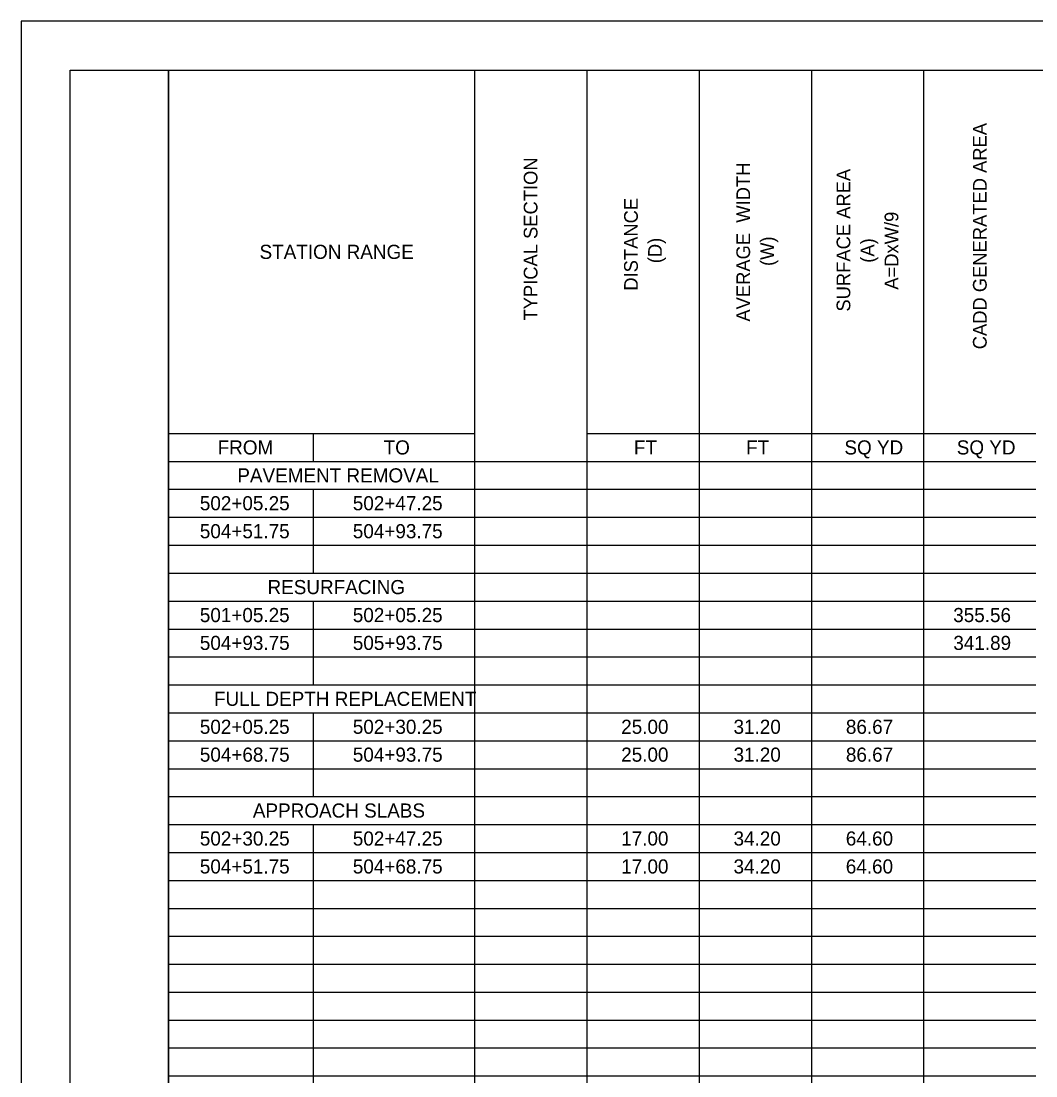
# Model space of a CAD drawing. Extents: x 0 to 34, y 0 to 22.
# Drawn here: x 0 to 10.32, y 11.28 to 22 of the extents above; entities that cross this region are included whole.
import ezdxf

# ---------------------------------------------------------------- set-up
doc = ezdxf.new("R2010")
doc.units = 0
for name, color, linetype in [('SH_Border', 7, 'Continuous'), ('SH_Cut_Line', 7, 'Continuous'), ('SH_Text', 7, 'Continuous')]:
    doc.layers.add(name, color=color, linetype=linetype)

msp = doc.modelspace()

# ---------------------------------------------------------------- linework, layer by layer
at = {"layer": 'SH_Border'}
for points in [[(0.5, 21.5), (1.5, 21.5), (1.5, 0.5), (0.5, 0.5)], [(1.5, 21.5), (33.5, 21.5), (33.5, 0.5), (1.5, 0.5)]]:
    msp.add_lwpolyline(points, close=True, dxfattribs=at)
at = {"layer": 'SH_Cut_Line'}
msp.add_lwpolyline([(0, 0), (34, 0), (34, 22), (0, 22)], close=True, dxfattribs=at)
at = {"layer": 'SH_Text'}
for p, q in [((1.5, 21.5), (2.969, 21.5)), ((1.5, 21.5), (1.5, 21.216)), ((2.969, 21.5), (4.609, 21.5)), ((4.609, 21.5), (8.033, 21.5)), ((4.609, 21.5), (4.609, 21.216)), ((5.75, 21.5), (5.75, 21.216)), ((6.892, 21.5), (6.892, 21.216)), ((8.033, 21.5), (10.315, 21.5)), ((8.033, 21.5), (8.033, 21.216)), ((9.174, 21.5), (9.174, 21.216)), ((1.5, 21.216), (1.5, 20.932)), ((4.609, 21.216), (4.609, 20.932)), ((5.75, 21.216), (5.75, 20.932)), ((6.892, 21.216), (6.892, 20.932)), ((8.033, 21.216), (8.033, 20.932)), ((9.174, 21.216), (9.174, 20.932)), ((1.5, 20.932), (1.5, 20.649)), ((4.609, 20.932), (4.609, 20.649)), ((5.75, 20.932), (5.75, 20.649)), ((6.892, 20.932), (6.892, 20.649)), ((8.033, 20.932), (8.033, 20.649)), ((9.174, 20.932), (9.174, 20.649)), ((1.5, 20.649), (1.5, 20.081)), ((4.609, 20.649), (4.609, 20.081)), ((5.75, 20.649), (5.75, 20.081)), ((6.892, 20.649), (6.892, 20.081)), ((8.033, 20.649), (8.033, 20.081)), ((9.174, 20.649), (9.174, 20.081)), ((1.5, 20.081), (1.5, 19.797)), ((4.609, 20.081), (4.609, 19.797)), ((5.75, 20.081), (5.75, 19.797)), ((6.892, 20.081), (6.892, 19.797)), ((8.033, 20.081), (8.033, 19.797)), ((9.174, 20.081), (9.174, 19.797)), ((1.5, 19.797), (1.5, 19.514)), ((4.609, 19.797), (4.609, 19.514)), ((5.75, 19.797), (5.75, 19.514)), ((6.892, 19.797), (6.892, 19.514)), ((8.033, 19.797), (8.033, 19.514)), ((9.174, 19.797), (9.174, 19.514)), ((1.5, 19.514), (1.5, 19.23)), ((4.609, 19.514), (4.609, 19.23)), ((5.75, 19.514), (5.75, 19.23)), ((6.892, 19.514), (6.892, 19.23)), ((8.033, 19.514), (8.033, 19.23)), ((9.174, 19.514), (9.174, 19.23)), ((1.5, 19.23), (1.5, 18.946)), ((4.609, 19.23), (4.609, 18.946)), ((5.75, 19.23), (5.75, 18.946)), ((6.892, 19.23), (6.892, 18.946)), ((8.033, 19.23), (8.033, 18.946)), ((9.174, 19.23), (9.174, 18.946)), ((1.5, 18.946), (1.5, 18.662)), ((4.609, 18.946), (4.609, 18.662)), ((5.75, 18.946), (5.75, 18.662)), ((6.892, 18.946), (6.892, 18.662)), ((8.033, 18.946), (8.033, 18.662)), ((9.174, 18.946), (9.174, 18.662)), ((1.5, 18.662), (1.5, 18.378)), ((4.609, 18.662), (4.609, 18.378)), ((5.75, 18.662), (5.75, 18.378)), ((6.892, 18.662), (6.892, 18.378)), ((8.033, 18.662), (8.033, 18.378)), ((9.174, 18.662), (9.174, 18.378)), ((1.5, 18.378), (1.5, 18.095)), ((4.609, 18.378), (4.609, 18.095)), ((5.75, 18.378), (5.75, 18.095)), ((6.892, 18.378), (6.892, 18.095)), ((8.033, 18.378), (8.033, 18.095)), ((9.174, 18.378), (9.174, 18.095)), ((1.5, 18.095), (1.5, 17.811)), ((4.609, 18.095), (4.609, 17.811)), ((5.75, 18.095), (5.75, 17.811)), ((6.892, 18.095), (6.892, 17.811)), ((8.033, 18.095), (8.033, 17.811)), ((9.174, 18.095), (9.174, 17.811)), ((1.5, 17.811), (2.969, 17.811)), ((1.5, 17.811), (1.5, 17.527)), ((2.969, 17.811), (4.609, 17.811)), ((2.969, 17.811), (2.969, 17.527)), ((4.609, 17.811), (4.609, 17.527)), ((5.75, 17.811), (8.033, 17.811)), ((5.75, 17.811), (5.75, 17.527)), ((6.892, 17.811), (6.892, 17.527)), ((8.033, 17.811), (10.315, 17.811)), ((8.033, 17.811), (8.033, 17.527)), ((9.174, 17.811), (9.174, 17.527)), ((1.5, 17.527), (2.969, 17.527)), ((1.5, 17.527), (1.5, 17.243)), ((2.969, 17.527), (4.609, 17.527)), ((4.609, 17.527), (8.033, 17.527)), ((4.609, 17.527), (4.609, 17.243)), ((5.75, 17.527), (5.75, 17.243)), ((6.892, 17.527), (6.892, 17.243)), ((8.033, 17.527), (10.315, 17.527)), ((8.033, 17.527), (8.033, 17.243)), ((9.174, 17.527), (9.174, 17.243)), ((1.5, 17.243), (2.969, 17.243)), ((1.5, 17.243), (1.5, 16.959)), ((2.969, 17.243), (4.609, 17.243)), ((2.969, 17.243), (2.969, 16.959)), ((4.609, 17.243), (8.033, 17.243)), ((4.609, 17.243), (4.609, 16.959)), ((5.75, 17.243), (5.75, 16.959)), ((6.892, 17.243), (6.892, 16.959)), ((8.033, 17.243), (10.315, 17.243)), ((8.033, 17.243), (8.033, 16.959)), ((9.174, 17.243), (9.174, 16.959)), ((1.5, 16.959), (2.969, 16.959)), ((1.5, 16.959), (1.5, 16.676)), ((2.969, 16.959), (4.609, 16.959)), ((2.969, 16.959), (2.969, 16.676)), ((4.609, 16.959), (8.033, 16.959)), ((4.609, 16.959), (4.609, 16.676)), ((5.75, 16.959), (5.75, 16.676)), ((6.892, 16.959), (6.892, 16.676)), ((8.033, 16.959), (10.315, 16.959)), ((8.033, 16.959), (8.033, 16.676)), ((9.174, 16.959), (9.174, 16.676)), ((1.5, 16.676), (2.969, 16.676)), ((1.5, 16.676), (1.5, 16.108)), ((2.969, 16.676), (4.609, 16.676)), ((2.969, 16.676), (2.969, 16.392)), ((4.609, 16.676), (8.033, 16.676)), ((4.609, 16.676), (4.609, 16.108)), ((5.75, 16.676), (5.75, 16.108)), ((6.892, 16.676), (6.892, 16.108)), ((8.033, 16.676), (10.315, 16.676)), ((8.033, 16.676), (8.033, 16.108)), ((9.174, 16.676), (9.174, 16.108)), ((1.5, 16.392), (2.969, 16.392)), ((2.969, 16.392), (4.609, 16.392)), ((4.609, 16.392), (8.033, 16.392)), ((8.033, 16.392), (10.315, 16.392)), ((1.5, 16.108), (2.969, 16.108)), ((1.5, 16.108), (1.5, 15.824)), ((2.969, 16.108), (4.609, 16.108)), ((2.969, 16.108), (2.969, 15.824)), ((4.609, 16.108), (8.033, 16.108)), ((4.609, 16.108), (4.609, 15.824)), ((5.75, 16.108), (5.75, 15.824)), ((6.892, 16.108), (6.892, 15.824)), ((8.033, 16.108), (10.315, 16.108)), ((8.033, 16.108), (8.033, 15.824)), ((9.174, 16.108), (9.174, 15.824)), ((1.5, 15.824), (2.969, 15.824)), ((1.5, 15.824), (1.5, 15.541)), ((2.969, 15.824), (4.609, 15.824)), ((2.969, 15.824), (2.969, 15.541)), ((4.609, 15.824), (8.033, 15.824)), ((4.609, 15.824), (4.609, 15.541)), ((5.75, 15.824), (5.75, 15.541)), ((6.892, 15.824), (6.892, 15.541)), ((8.033, 15.824), (10.315, 15.824)), ((8.033, 15.824), (8.033, 15.541)), ((9.174, 15.824), (9.174, 15.541)), ((1.5, 15.541), (2.969, 15.541)), ((1.5, 15.541), (1.5, 15.257)), ((2.969, 15.541), (4.609, 15.541)), ((2.969, 15.541), (2.969, 15.257)), ((4.609, 15.541), (8.033, 15.541)), ((4.609, 15.541), (4.609, 15.257)), ((5.75, 15.541), (5.75, 15.257)), ((6.892, 15.541), (6.892, 15.257)), ((8.033, 15.541), (10.315, 15.541)), ((8.033, 15.541), (8.033, 15.257)), ((9.174, 15.541), (9.174, 15.257)), ((1.5, 15.257), (2.969, 15.257)), ((1.5, 15.257), (1.5, 14.689)), ((2.969, 15.257), (4.609, 15.257)), ((4.609, 15.257), (8.033, 15.257)), ((4.609, 15.257), (4.609, 14.689)), ((5.75, 15.257), (5.75, 14.689)), ((6.892, 15.257), (6.892, 14.689)), ((8.033, 15.257), (10.315, 15.257)), ((8.033, 15.257), (8.033, 14.689)), ((9.174, 15.257), (9.174, 14.689)), ((1.5, 14.973), (2.969, 14.973)), ((2.969, 14.973), (4.609, 14.973)), ((2.969, 14.973), (2.969, 14.689)), ((4.609, 14.973), (8.033, 14.973)), ((8.033, 14.973), (10.315, 14.973)), ((1.5, 14.689), (2.969, 14.689)), ((1.5, 14.689), (1.5, 14.405)), ((2.969, 14.689), (4.609, 14.689)), ((2.969, 14.689), (2.969, 14.405)), ((4.609, 14.689), (8.033, 14.689)), ((4.609, 14.689), (4.609, 14.405)), ((5.75, 14.689), (5.75, 14.405)), ((6.892, 14.689), (6.892, 14.405)), ((8.033, 14.689), (10.315, 14.689)), ((8.033, 14.689), (8.033, 14.405)), ((9.174, 14.689), (9.174, 14.405)), ((1.5, 14.405), (2.969, 14.405)), ((1.5, 14.405), (1.5, 14.122)), ((2.969, 14.405), (4.609, 14.405)), ((2.969, 14.405), (2.969, 14.122)), ((4.609, 14.405), (8.033, 14.405)), ((4.609, 14.405), (4.609, 14.122)), ((5.75, 14.405), (5.75, 14.122)), ((6.892, 14.405), (6.892, 14.122)), ((8.033, 14.405), (10.315, 14.405)), ((8.033, 14.405), (8.033, 14.122)), ((9.174, 14.405), (9.174, 14.122)), ((1.5, 14.122), (2.969, 14.122)), ((1.5, 14.122), (1.5, 13.838)), ((2.969, 14.122), (4.609, 14.122)), ((4.609, 14.122), (8.033, 14.122)), ((4.609, 14.122), (4.609, 13.838)), ((5.75, 14.122), (5.75, 13.838)), ((6.892, 14.122), (6.892, 13.838)), ((8.033, 14.122), (10.315, 14.122)), ((8.033, 14.122), (8.033, 13.838)), ((9.174, 14.122), (9.174, 13.838)), ((1.5, 13.838), (2.969, 13.838)), ((1.5, 13.838), (1.5, 12.986)), ((2.969, 13.838), (4.609, 13.838)), ((2.969, 13.838), (2.969, 12.986)), ((4.609, 13.838), (8.033, 13.838)), ((4.609, 13.838), (4.609, 12.986)), ((5.75, 13.838), (5.75, 12.986)), ((6.892, 13.838), (6.892, 12.986)), ((8.033, 13.838), (10.315, 13.838)), ((8.033, 13.838), (8.033, 12.986)), ((9.174, 13.838), (9.174, 12.986)), ((1.5, 13.554), (2.969, 13.554)), ((2.969, 13.554), (4.609, 13.554)), ((4.609, 13.554), (8.033, 13.554)), ((8.033, 13.554), (10.315, 13.554)), ((1.5, 13.27), (2.969, 13.27)), ((2.969, 13.27), (4.609, 13.27)), ((4.609, 13.27), (8.033, 13.27)), ((8.033, 13.27), (10.315, 13.27)), ((1.5, 12.986), (2.969, 12.986)), ((1.5, 12.986), (1.5, 12.703)), ((2.969, 12.986), (4.609, 12.986)), ((2.969, 12.986), (2.969, 12.703)), ((4.609, 12.986), (8.033, 12.986)), ((4.609, 12.986), (4.609, 12.703)), ((5.75, 12.986), (5.75, 12.703)), ((6.892, 12.986), (6.892, 12.703)), ((8.033, 12.986), (10.315, 12.986)), ((8.033, 12.986), (8.033, 12.703)), ((9.174, 12.986), (9.174, 12.703)), ((1.5, 12.703), (2.969, 12.703)), ((1.5, 12.703), (1.5, 11.568)), ((2.969, 12.703), (4.609, 12.703)), ((2.969, 12.703), (2.969, 11.568)), ((4.609, 12.703), (8.033, 12.703)), ((4.609, 12.703), (4.609, 11.568)), ((5.75, 12.703), (5.75, 11.568)), ((6.892, 12.703), (6.892, 11.568)), ((8.033, 12.703), (10.315, 12.703)), ((8.033, 12.703), (8.033, 11.568)), ((9.174, 12.703), (9.174, 11.568)), ((1.5, 12.419), (2.969, 12.419)), ((2.969, 12.419), (4.609, 12.419)), ((4.609, 12.419), (8.033, 12.419)), ((8.033, 12.419), (10.315, 12.419)), ((1.5, 12.135), (2.969, 12.135)), ((2.969, 12.135), (4.609, 12.135)), ((4.609, 12.135), (8.033, 12.135)), ((8.033, 12.135), (10.315, 12.135)), ((1.5, 11.851), (2.969, 11.851)), ((2.969, 11.851), (4.609, 11.851)), ((4.609, 11.851), (8.033, 11.851)), ((8.033, 11.851), (10.315, 11.851)), ((1.5, 11.568), (2.969, 11.568)), ((1.5, 11.568), (1.5, 11.284)), ((2.969, 11.568), (4.609, 11.568)), ((2.969, 11.568), (2.969, 11.284)), ((4.609, 11.568), (8.033, 11.568)), ((4.609, 11.568), (4.609, 11.284)), ((5.75, 11.568), (5.75, 11.284)), ((6.892, 11.568), (6.892, 11.284)), ((8.033, 11.568), (10.315, 11.568)), ((8.033, 11.568), (8.033, 11.284)), ((9.174, 11.568), (9.174, 11.284)), ((1.5, 11.284), (2.969, 11.284)), ((1.5, 11.284), (1.5, 10.149)), ((2.969, 11.284), (4.609, 11.284)), ((2.969, 11.284), (2.969, 10.149)), ((4.609, 11.284), (8.033, 11.284)), ((4.609, 11.284), (4.609, 10.149)), ((5.75, 11.284), (5.75, 10.149)), ((6.892, 11.284), (6.892, 10.149)), ((8.033, 11.284), (10.315, 11.284)), ((8.033, 11.284), (8.033, 10.149)), ((9.174, 11.284), (9.174, 10.149))]:
    msp.add_line(p, q, dxfattribs=at)

# ---------------------------------------------------------------- texts
for s, height, p in [('CADD GENERATED AREA', 0.13938, (9.815, 18.666)), ('TYPICAL SECTION', 0.13938, (5.249, 18.958)), ('AVERAGE  WIDTH', 0.13938, (7.41, 18.947)), ('SURFACE AREA', 0.13938, (8.429, 19.049)), ('DISTANCE', 0.1394, (6.269, 19.261)), ('A=DxW/9', 0.1394, (8.917, 19.271)), ('(D)', 0.1394, (6.513, 19.54)), ('(W)', 0.1394, (7.654, 19.512)), ('(A)', 0.1394, (8.673, 19.545))]:
    msp.add_text(s, height=height, rotation=90, dxfattribs=at).set_placement(p)
for s, height, p in [('STATION RANGE', 0.14358, (2.424, 19.584)), ('FROM', 0.1436, (1.998, 17.597)), ('TO', 0.1436, (3.685, 17.597)), ('FT', 0.1436, (6.229, 17.597)), ('FT', 0.1436, (7.37, 17.597)), ('SQ YD', 0.1436, (8.369, 17.597)), ('SQ YD', 0.1436, (9.511, 17.597)), ('PAVEMENT REMOVAL', 0.14358, (2.198, 17.313)), ('502+05.25', 0.1436, (1.817, 17.03)), ('502+47.25', 0.1436, (3.372, 17.03)), ('504+51.75', 0.1436, (1.817, 16.746)), ('504+93.75', 0.1436, (3.372, 16.746)), ('RESURFACING', 0.14358, (2.505, 16.178)), ('501+05.25', 0.1436, (1.817, 15.894)), ('502+05.25', 0.1436, (3.372, 15.894)), ('355.56', 0.1436, (9.475, 15.894)), ('504+93.75', 0.1436, (1.817, 15.611)), ('505+93.75', 0.1436, (3.372, 15.611)), ('341.89', 0.1436, (9.476, 15.611)), ('FULL DEPTH REPLACEMENT', 0.14358, (1.961, 15.043)), ('502+05.25', 0.1436, (1.817, 14.759)), ('502+30.25', 0.1436, (3.372, 14.759)), ('25.00', 0.1436, (6.1, 14.759)), ('31.20', 0.1436, (7.242, 14.759)), ('86.67', 0.1436, (8.384, 14.759)), ('504+68.75', 0.1436, (1.817, 14.476)), ('504+93.75', 0.1436, (3.372, 14.476)), ('25.00', 0.1436, (6.1, 14.476)), ('31.20', 0.1436, (7.242, 14.476)), ('86.67', 0.1436, (8.384, 14.476)), ('APPROACH SLABS', 0.14358, (2.356, 13.908)), ('502+30.25', 0.1436, (1.817, 13.624)), ('502+47.25', 0.1436, (3.372, 13.624)), ('17.00', 0.1436, (6.1, 13.624)), ('34.20', 0.1436, (7.242, 13.624)), ('64.60', 0.1436, (8.383, 13.624)), ('504+51.75', 0.1436, (1.817, 13.34)), ('504+68.75', 0.1436, (3.372, 13.34)), ('17.00', 0.1436, (6.1, 13.34)), ('34.20', 0.1436, (7.242, 13.34)), ('64.60', 0.1436, (8.383, 13.34))]:
    msp.add_text(s, height=height, dxfattribs=at).set_placement(p)

doc.saveas('drawing.dxf')
